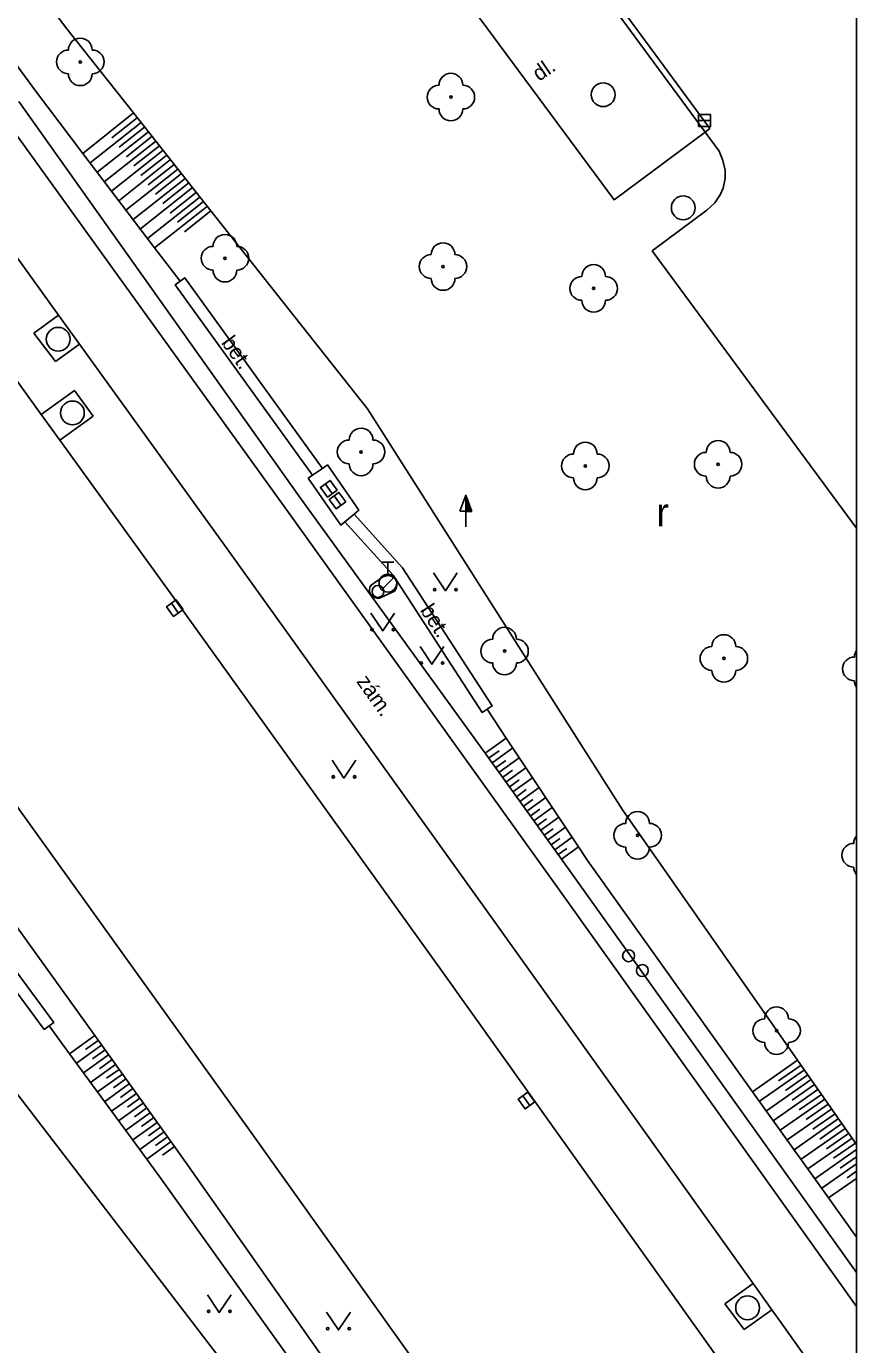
# Model space of a CAD drawing. Extents: x -596024 to -594475, y -1163820 to -1161957.
# Drawn here: x -594510.4 to -594475.5, y -1163358.2 to -1163302.7 of the extents above; entities that cross this region are included whole.
import ezdxf

# ---------------------------------------------------------------- set-up
doc = ezdxf.new("R2010")
doc.units = 0
for name, color, linetype in [('Level 10', 7, 'Continuous'), ('Level 11', 7, 'Continuous'), ('Level 14', 7, 'Continuous'), ('Level 15', 7, 'Continuous'), ('Level 22', 7, 'Continuous'), ('Level 25', 7, 'Continuous'), ('Level 27', 7, 'Continuous'), ('Level 28', 7, 'Continuous'), ('Level 36', 7, 'Continuous'), ('Level 40', 7, 'Continuous'), ('Vrstva 63', 7, 'Continuous')]:
    doc.layers.add(name, color=color, linetype=linetype)

msp = doc.modelspace()

# ---------------------------------------------------------------- linework, layer by layer
at = {"layer": 'Level 10'}
msp.add_line((-594484.08, -1163312.13), (-594475.47, -1163323.791), dxfattribs=at)
for points in [[(-594496.39, -1163295.49), (-594485.68, -1163309.98), (-594481.85, -1163307.13)], [(-594481.85, -1163307.13), (-594481.26, -1163307.94)], [(-594481.26, -1163307.94), (-594481.11, -1163308.28), (-594481, -1163308.72), (-594481, -1163309.09), (-594481.09, -1163309.49), (-594481.22, -1163309.78), (-594481.44, -1163310.11), (-594481.78, -1163310.42), (-594484.08, -1163312.13)], [(-594516.19, -1163310.14), (-594509.79, -1163319.01)], [(-594509.79, -1163319.01), (-594509.01, -1163320.1)], [(-594509.01, -1163320.1), (-594504.33, -1163326.58)], [(-594504.33, -1163326.58), (-594492.87, -1163342.51)], [(-594512.54, -1163333.11), (-594501.03, -1163349.12)], [(-594492.87, -1163342.51), (-594481.02, -1163359.13)], [(-594501.03, -1163349.12), (-594489.53, -1163365.23)]]:
    msp.add_lwpolyline(points, dxfattribs=at)
at = {"layer": 'Level 11'}
for p, q in [((-594476.27, -1163355.43), (-594475.47, -1163356.552)), ((-594478.6, -1163357.29), (-594475.47, -1163361.683))]:
    msp.add_line(p, q, dxfattribs=at)
for points in [[(-594658.25, -1163068.41), (-594648.78, -1163081.26), (-594637.52, -1163096.5), (-594627.94, -1163109.39), (-594616.36, -1163125.13), (-594603.5, -1163142.69), (-594587.25, -1163164.52), (-594574.42, -1163181.74), (-594559, -1163202.7), (-594543.73, -1163223.28), (-594530.41, -1163241.31), (-594518.2, -1163257.82), (-594506.57, -1163273.57), (-594492.81, -1163292.25), (-594492.53, -1163292.63), (-594483.61, -1163304.74), (-594481.85, -1163307.13)], [(-594657.91, -1163068.45), (-594648.58, -1163081.11), (-594637.31, -1163096.34), (-594627.74, -1163109.24), (-594616.16, -1163124.98), (-594603.29, -1163142.54), (-594587.04, -1163164.37), (-594574.22, -1163181.58), (-594558.79, -1163202.55), (-594543.52, -1163223.13), (-594530.21, -1163241.16), (-594518, -1163257.67), (-594506.37, -1163273.42), (-594492.33, -1163292.48), (-594481.65, -1163306.98), (-594481.85, -1163307.13)], [(-594511.42, -1163306.43), (-594499.53, -1163322.94)], [(-594513.84, -1163308.22), (-594509.06, -1163314.84)], [(-594498.38, -1163321.57), (-594504.15, -1163313.56), (-594503.95, -1163313.41)], [(-594503.95, -1163313.41), (-594503.75, -1163313.26), (-594497.96, -1163321.29)], [(-594509.06, -1163314.84), (-594510.11, -1163315.6)], [(-594509.06, -1163314.84), (-594508.18, -1163316.05)], [(-594510.11, -1163315.6), (-594509.2, -1163316.79)], [(-594509.2, -1163316.79), (-594508.18, -1163316.05)], [(-594508.18, -1163316.05), (-594501.89, -1163324.76)], [(-594508.4, -1163318.01), (-594509.79, -1163319.01)], [(-594507.61, -1163319.09), (-594508.4, -1163318.01)], [(-594509.01, -1163320.1), (-594507.61, -1163319.09)], [(-594497.96, -1163321.29), (-594497.75, -1163321.14), (-594496.42, -1163323.04), (-594496.62, -1163323.21)], [(-594498.56, -1163321.7), (-594498.38, -1163321.57)], [(-594497.01, -1163323.53), (-594497.18, -1163323.67), (-594498.56, -1163321.7)], [(-594498.38, -1163321.57), (-594497.96, -1163321.29)], [(-594499.53, -1163322.94), (-594488.09, -1163338.88)], [(-594496.62, -1163323.21), (-594497.01, -1163323.53)], [(-594496.62, -1163323.21), (-594494.58, -1163325.47), (-594490.81, -1163331.28), (-594491.02, -1163331.42)], [(-594491.02, -1163331.42), (-594491.23, -1163331.56), (-594494.98, -1163325.77), (-594497.01, -1163323.53)], [(-594501.89, -1163324.76), (-594490.62, -1163340.49)], [(-594495.55, -1163326.74), (-594495.66, -1163326.75), (-594495.76, -1163326.72), (-594495.85, -1163326.67), (-594495.92, -1163326.59), (-594495.97, -1163326.49), (-594495.98, -1163326.39), (-594495.96, -1163326.28), (-594495.91, -1163326.19)], [(-594495.91, -1163326.19), (-594495.42, -1163325.85)], [(-594495.42, -1163325.85), (-594495.28, -1163325.8), (-594495.14, -1163325.79), (-594495.01, -1163325.84), (-594494.9, -1163325.93), (-594494.83, -1163326.06), (-594494.82, -1163326.2), (-594494.85, -1163326.33), (-594494.93, -1163326.45)], [(-594495.55, -1163326.74), (-594494.93, -1163326.45)], [(-594515.12, -1163336.67), (-594509.27, -1163344.59), (-594509.46, -1163344.74)], [(-594509.46, -1163344.74), (-594509.67, -1163344.89), (-594515.53, -1163336.96)], [(-594488.09, -1163338.88), (-594476.27, -1163355.43)], [(-594490.62, -1163340.49), (-594479.83, -1163355.58)], [(-594479.83, -1163355.58), (-594481.02, -1163356.43)], [(-594479.83, -1163355.58), (-594479.04, -1163356.68)], [(-594481.02, -1163356.43), (-594480.2, -1163357.51)], [(-594480.2, -1163357.51), (-594479.04, -1163356.68)], [(-594479.04, -1163356.68), (-594478.6, -1163357.29)]]:
    msp.add_lwpolyline(points, dxfattribs=at)
at = {"layer": 'Level 14'}
for p, q in [((-594487.89, -1163337.73), (-594475.47, -1163355.122)), ((-594475.47, -1163353.632), (-594476.65, -1163351.98))]:
    msp.add_line(p, q, dxfattribs=at)
for points in [[(-594521.39, -1163286.06), (-594508.71, -1163302.79)], [(-594508.71, -1163302.79), (-594505.91, -1163306.33), (-594502.65, -1163310.45)], [(-594511.38, -1163303.56), (-594510.04, -1163305.4)], [(-594510.04, -1163305.4), (-594508.04, -1163308.03), (-594505.02, -1163312.01)], [(-594510.73, -1163305.84), (-594498.92, -1163322.48)], [(-594502.65, -1163310.45), (-594496.06, -1163318.77)], [(-594505.02, -1163312.01), (-594503.95, -1163313.41)], [(-594496.06, -1163318.77), (-594485.32, -1163335.65)], [(-594498.92, -1163322.48), (-594491.11, -1163333.27), (-594487.89, -1163337.73)], [(-594487.18, -1163337.21), (-594490.22, -1163332.63), (-594491.02, -1163331.42)], [(-594504.18, -1163349.81), (-594507.54, -1163345.14), (-594514.89, -1163334.93)], [(-594485.32, -1163335.65), (-594477.96, -1163346.18), (-594475.47, -1163349.734)], [(-594486.8, -1163337.78), (-594487.18, -1163337.21)], [(-594518.64, -1163337.42), (-594499.82, -1163361.92), (-594495.09, -1163368.06)], [(-594476.65, -1163351.98), (-594479.85, -1163347.51), (-594486.8, -1163337.78)], [(-594505.35, -1163350.35), (-594508.6, -1163345.91), (-594509.46, -1163344.74)], [(-594503.63, -1163350.58), (-594504.18, -1163349.81)], [(-594504.64, -1163351.32), (-594505.35, -1163350.35)], [(-594492.13, -1163366.95), (-594503.63, -1163350.58)], [(-594493.68, -1163366.66), (-594498.04, -1163360.56), (-594504.64, -1163351.32)]]:
    msp.add_lwpolyline(points, dxfattribs=at)
at = {"layer": 'Level 15'}
for p, q in [((-594475.47, -1163349.933), (-594477.23, -1163351.17)), ((-594475.47, -1163350.545), (-594476.94, -1163351.57)), ((-594475.47, -1163350.245), (-594476.16, -1163350.72)), ((-594475.47, -1163351.157), (-594476.65, -1163351.98)), ((-594475.47, -1163350.852), (-594475.87, -1163351.13))]:
    msp.add_line(p, q, dxfattribs=at)
for points in [[(-594505.91, -1163306.33), (-594508.04, -1163308.03)], [(-594505.59, -1163306.73), (-594507.74, -1163308.43)], [(-594505.75, -1163306.53), (-594506.82, -1163307.38)], [(-594505.28, -1163307.12), (-594507.44, -1163308.82)], [(-594505.44, -1163306.92), (-594506.51, -1163307.77)], [(-594505.13, -1163307.31), (-594506.21, -1163308.17)], [(-594504.97, -1163307.51), (-594507.14, -1163309.22)], [(-594504.66, -1163307.9), (-594506.83, -1163309.62)], [(-594504.82, -1163307.71), (-594505.9, -1163308.56)], [(-594504.35, -1163308.29), (-594506.53, -1163310.02)], [(-594504.51, -1163308.1), (-594505.6, -1163308.96)], [(-594504.04, -1163308.69), (-594506.23, -1163310.42)], [(-594504.2, -1163308.49), (-594505.29, -1163309.35)], [(-594503.89, -1163308.88), (-594504.98, -1163309.75)], [(-594503.73, -1163309.08), (-594505.92, -1163310.81)], [(-594503.42, -1163309.47), (-594505.62, -1163311.21)], [(-594503.58, -1163309.27), (-594504.68, -1163310.14)], [(-594503.11, -1163309.86), (-594505.32, -1163311.61)], [(-594503.27, -1163309.67), (-594504.37, -1163310.54)], [(-594502.96, -1163310.06), (-594504.06, -1163310.93)], [(-594502.8, -1163310.25), (-594505.02, -1163312.01)], [(-594502.65, -1163310.45), (-594503.76, -1163311.33)], [(-594491.11, -1163333.27), (-594490.22, -1163332.63)], [(-594490.97, -1163333.48), (-594490.52, -1163333.16)], [(-594490.82, -1163333.68), (-594489.94, -1163333.04)], [(-594490.67, -1163333.88), (-594490.24, -1163333.57)], [(-594490.53, -1163334.08), (-594489.67, -1163333.46)], [(-594490.38, -1163334.29), (-594489.95, -1163333.98)], [(-594490.23, -1163334.49), (-594489.39, -1163333.88)], [(-594490.09, -1163334.69), (-594489.67, -1163334.39)], [(-594489.94, -1163334.89), (-594489.11, -1163334.3)], [(-594489.79, -1163335.1), (-594489.38, -1163334.8)], [(-594489.65, -1163335.3), (-594488.84, -1163334.71)], [(-594489.5, -1163335.5), (-594489.1, -1163335.21)], [(-594489.35, -1163335.7), (-594488.56, -1163335.13)], [(-594489.21, -1163335.91), (-594488.81, -1163335.62)], [(-594489.06, -1163336.11), (-594488.28, -1163335.55)], [(-594488.91, -1163336.31), (-594488.53, -1163336.03)], [(-594488.77, -1163336.51), (-594488.01, -1163335.96)], [(-594488.62, -1163336.72), (-594488.24, -1163336.45)], [(-594488.48, -1163336.92), (-594487.73, -1163336.38)], [(-594488.33, -1163337.12), (-594487.96, -1163336.86)], [(-594488.18, -1163337.33), (-594487.45, -1163336.8)], [(-594488.04, -1163337.53), (-594487.67, -1163337.27)], [(-594487.89, -1163337.73), (-594487.18, -1163337.21)], [(-594507.54, -1163345.14), (-594508.6, -1163345.91)], [(-594507.25, -1163345.55), (-594508.31, -1163346.31)], [(-594507.4, -1163345.35), (-594507.93, -1163345.73)], [(-594506.96, -1163345.96), (-594508.01, -1163346.72)], [(-594507.1, -1163345.75), (-594507.63, -1163346.13)], [(-594506.81, -1163346.16), (-594507.34, -1163346.54)], [(-594477.96, -1163346.18), (-594479.85, -1163347.51)], [(-594506.67, -1163346.36), (-594507.72, -1163347.12)], [(-594506.52, -1163346.57), (-594507.04, -1163346.94)], [(-594477.67, -1163346.59), (-594479.56, -1163347.91)], [(-594477.81, -1163346.39), (-594478.76, -1163347.05)], [(-594506.37, -1163346.77), (-594507.42, -1163347.52)], [(-594506.08, -1163347.17), (-594507.13, -1163347.93)], [(-594506.23, -1163346.97), (-594506.75, -1163347.35)], [(-594477.38, -1163347), (-594479.27, -1163348.32)], [(-594477.53, -1163346.8), (-594478.47, -1163347.46)], [(-594477.24, -1163347.21), (-594478.18, -1163347.86)], [(-594505.79, -1163347.58), (-594506.83, -1163348.33)], [(-594505.94, -1163347.38), (-594506.46, -1163347.75)], [(-594505.64, -1163347.78), (-594506.16, -1163348.16)], [(-594477.1, -1163347.41), (-594478.98, -1163348.73)], [(-594476.81, -1163347.82), (-594478.69, -1163349.13)], [(-594476.95, -1163347.62), (-594477.89, -1163348.27)], [(-594505.5, -1163347.99), (-594506.54, -1163348.73)], [(-594505.2, -1163348.39), (-594506.24, -1163349.14)], [(-594505.35, -1163348.19), (-594505.87, -1163348.56)], [(-594476.52, -1163348.23), (-594478.4, -1163349.54)], [(-594476.67, -1163348.03), (-594477.6, -1163348.68)], [(-594504.91, -1163348.8), (-594505.94, -1163349.54)], [(-594505.06, -1163348.59), (-594505.58, -1163348.97)], [(-594476.24, -1163348.64), (-594478.1, -1163349.95)], [(-594476.38, -1163348.44), (-594477.31, -1163349.09)], [(-594476.09, -1163348.85), (-594477.02, -1163349.5)], [(-594504.62, -1163349.2), (-594505.65, -1163349.94)], [(-594504.77, -1163349), (-594505.28, -1163349.37)], [(-594504.48, -1163349.41), (-594504.99, -1163349.77)], [(-594475.95, -1163349.05), (-594477.81, -1163350.35)], [(-594475.66, -1163349.46), (-594477.52, -1163350.76)], [(-594475.81, -1163349.26), (-594476.74, -1163349.91)], [(-594504.33, -1163349.61), (-594505.35, -1163350.35)], [(-594504.18, -1163349.81), (-594504.69, -1163350.18)], [(-594475.52, -1163349.67), (-594476.45, -1163350.31)]]:
    msp.add_lwpolyline(points, dxfattribs=at)
at = {"layer": 'Level 22'}
for centre in [(-594508.15, -1163304.18), (-594492.55, -1163305.66), (-594502.06, -1163312.44), (-594492.88, -1163312.79), (-594486.54, -1163313.71), (-594496.33, -1163320.59), (-594486.89, -1163321.18), (-594481.3, -1163321.11), (-594490.29, -1163328.97), (-594481.06, -1163329.28), (-594484.69, -1163336.72), (-594478.84, -1163344.94)]:
    msp.add_circle(centre, 0.05, dxfattribs=at)
for centre, start, end in [((-594508.15, -1163303.68), 0, 180), ((-594508.65, -1163304.18), 90, 270), ((-594507.65, -1163304.18), 270, 90), ((-594508.15, -1163304.68), 180, 0), ((-594493.05, -1163305.66), 90, 270), ((-594492.55, -1163305.16), 0, 180), ((-594492.05, -1163305.66), 270, 90), ((-594492.55, -1163306.16), 180, 0), ((-594502.06, -1163311.94), 0, 180), ((-594492.88, -1163312.29), 0, 180), ((-594502.56, -1163312.44), 90, 270), ((-594501.56, -1163312.44), 270, 90), ((-594493.38, -1163312.79), 90, 270), ((-594492.38, -1163312.79), 270, 90), ((-594486.54, -1163313.21), 0, 180), ((-594502.06, -1163312.94), 180, 0), ((-594492.88, -1163313.29), 180, 0), ((-594487.04, -1163313.71), 90, 270), ((-594486.04, -1163313.71), 270, 90), ((-594486.54, -1163314.21), 180, 0), ((-594496.83, -1163320.59), 90, 270), ((-594496.33, -1163320.09), 0, 180), ((-594495.83, -1163320.59), 270, 90), ((-594481.3, -1163320.61), 0, 180), ((-594487.39, -1163321.18), 90, 270), ((-594486.89, -1163320.68), 0, 180), ((-594486.39, -1163321.18), 270, 90), ((-594481.8, -1163321.11), 90, 270), ((-594480.8, -1163321.11), 270, 90), ((-594496.33, -1163321.09), 180, 0), ((-594486.89, -1163321.68), 180, 0), ((-594481.3, -1163321.61), 180, 0), ((-594490.29, -1163328.47), 0, 180), ((-594481.06, -1163328.78), 0, 180), ((-594490.79, -1163328.97), 90, 270), ((-594489.79, -1163328.97), 270, 90), ((-594481.56, -1163329.28), 90, 270), ((-594480.56, -1163329.28), 270, 90), ((-594475.06, -1163329.22), 145.0848, 180), ((-594490.29, -1163329.47), 180, 0), ((-594475.56, -1163329.72), 90, 270), ((-594481.06, -1163329.78), 180, 0), ((-594475.06, -1163330.22), 180, 214.9152), ((-594485.19, -1163336.72), 90, 270), ((-594484.69, -1163336.22), 0, 180), ((-594484.19, -1163336.72), 270, 90), ((-594475.09, -1163337.06), 139.4642, 180), ((-594484.69, -1163337.22), 180, 0), ((-594475.59, -1163337.56), 90, 270), ((-594475.09, -1163338.06), 180, 220.5358), ((-594478.84, -1163344.44), 0, 180), ((-594479.34, -1163344.94), 90, 270), ((-594478.34, -1163344.94), 270, 90), ((-594478.84, -1163345.44), 180, 0)]:
    msp.add_arc(centre, 0.5, start, end, dxfattribs=at)
at = {"layer": 'Level 25'}
for p, q in [((-594492.172, -1163323.088), (-594491.92, -1163322.414)), ((-594491.92, -1163323.088), (-594492.172, -1163323.088)), ((-594491.92, -1163323.74), (-594491.92, -1163323.09))]:
    msp.add_line(p, q, dxfattribs=at)
for points in [[(-594491.67, -1163323.09), (-594491.92, -1163323.09), (-594491.92, -1163322.414), (-594491.92, -1163322.414)], [(-594491.727, -1163323.05), (-594491.88, -1163323.05), (-594491.88, -1163322.637)], [(-594491.785, -1163323.01), (-594491.84, -1163323.01), (-594491.84, -1163322.861)]]:
    msp.add_lwpolyline(points, close=True, dxfattribs=at)
at = {"layer": 'Level 27'}
for p, q in [((-594482.12, -1163306.65), (-594481.62, -1163306.65)), ((-594497.543, -1163322.342), (-594497.837, -1163321.938)), ((-594497.173, -1163322.842), (-594497.467, -1163322.438)), ((-594504.023, -1163327.362), (-594504.317, -1163326.958)), ((-594489.223, -1163348.082), (-594489.517, -1163347.678))]:
    msp.add_line(p, q, dxfattribs=at)
for points in [[(-594482.12, -1163306.9), (-594481.62, -1163306.9), (-594481.62, -1163306.4), (-594482.12, -1163306.4)], [(-594497.341, -1163322.195), (-594497.635, -1163321.791), (-594498.039, -1163322.085), (-594497.745, -1163322.489)], [(-594496.971, -1163322.695), (-594497.265, -1163322.291), (-594497.669, -1163322.585), (-594497.375, -1163322.989)], [(-594503.821, -1163327.215), (-594504.115, -1163326.811), (-594504.519, -1163327.105), (-594504.225, -1163327.509)], [(-594489.021, -1163347.935), (-594489.315, -1163347.531), (-594489.719, -1163347.825), (-594489.425, -1163348.229)]]:
    msp.add_lwpolyline(points, close=True, dxfattribs=at)
for centre in [(-594486.14, -1163305.56), (-594482.77, -1163310.32), (-594509.08, -1163315.85), (-594508.48, -1163318.95), (-594480.06, -1163356.6)]:
    msp.add_circle(centre, 0.5, dxfattribs=at)
at = {"layer": 'Level 28'}
for p, q in [((-594495.45, -1163325.235), (-594494.95, -1163325.235)), ((-594495.2, -1163325.735), (-594495.2, -1163325.235)), ((-594495.458, -1163326.382), (-594494.928, -1163325.852))]:
    msp.add_line(p, q, dxfattribs=at)
for centre, radius in [((-594495.62, -1163326.46), 0.25), ((-594495.2, -1163326.11), 0.375), ((-594485.07, -1163341.79), 0.25), ((-594484.49, -1163342.41), 0.25)]:
    msp.add_circle(centre, radius, dxfattribs=at)
at = {"layer": 'Level 36'}
for points in [[(-594493.28, -1163325.68), (-594492.78, -1163326.43), (-594492.28, -1163325.68)], [(-594495.92, -1163327.37), (-594495.42, -1163328.12), (-594494.92, -1163327.37)], [(-594493.85, -1163328.77), (-594493.35, -1163329.52), (-594492.85, -1163328.77)], [(-594497.55, -1163333.56), (-594497.05, -1163334.31), (-594496.55, -1163333.56)], [(-594502.8, -1163356.05), (-594502.3, -1163356.8), (-594501.8, -1163356.05)], [(-594497.78, -1163356.78), (-594497.28, -1163357.53), (-594496.78, -1163356.78)]]:
    msp.add_lwpolyline(points, dxfattribs=at)
for centre in [(-594493.23, -1163326.38), (-594492.331, -1163326.38), (-594495.87, -1163328.07), (-594494.971, -1163328.07), (-594493.8, -1163329.47), (-594492.901, -1163329.47), (-594497.5, -1163334.26), (-594496.601, -1163334.26), (-594502.75, -1163356.75), (-594501.851, -1163356.75), (-594497.73, -1163357.48), (-594496.831, -1163357.48)]:
    msp.add_circle(centre, 0.05, dxfattribs=at)
at = {"layer": 'Vrstva 63'}
msp.add_lwpolyline([(-594475.47, -1163820.23), (-596024.42, -1163820.23), (-596024.42, -1161956.88), (-594475.47, -1161956.88)], close=True, dxfattribs=at)

# ---------------------------------------------------------------- texts
at = {"layer": 'Level 36'}
msp.add_text('r', height=1.2, dxfattribs=at).set_placement((-594483.903, -1163323.727))
at = {"layer": 'Level 40'}
for s, rotation, p in [('dl.', 34.08, (-594488.84, -1163305.02)), ('bet.', 305.77, (-594502.24, -1163316)), ('bet.', 302.95, (-594493.87, -1163327.25)), ('zám.', 305.47, (-594496.55, -1163330.25))]:
    msp.add_text(s, height=0.65, rotation=rotation, dxfattribs=at).set_placement(p)

doc.saveas('drawing.dxf')
